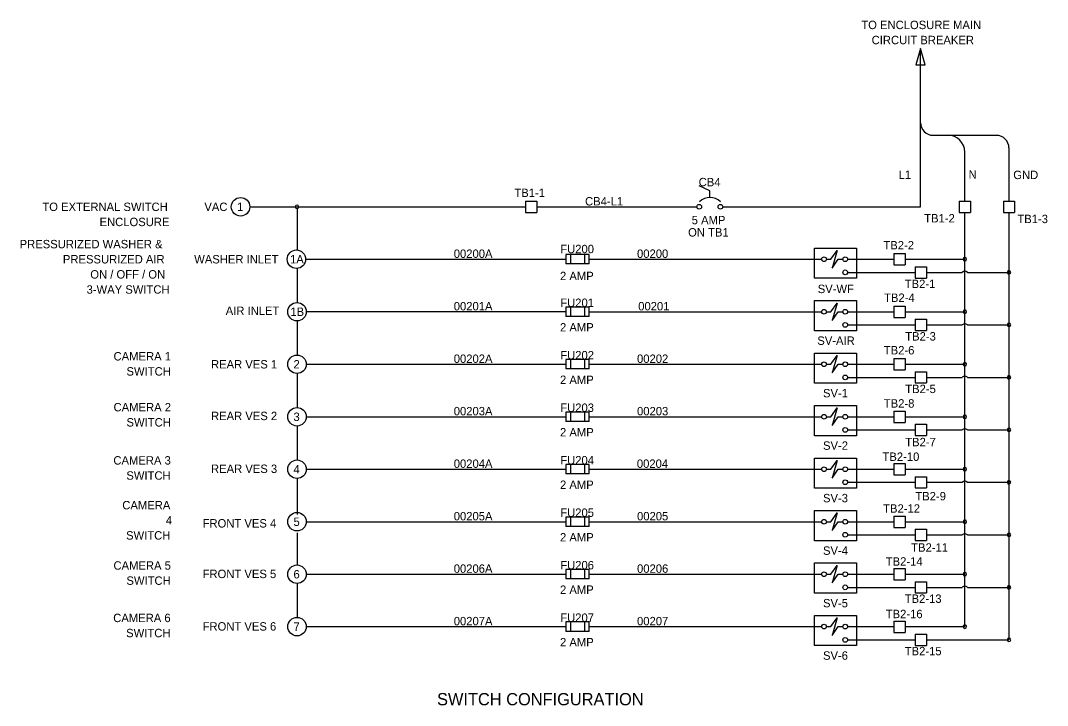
# Model space of a CAD drawing. Extents: x 0.81 to 2.03, y 0.91 to 1.72.
import ezdxf

# ---------------------------------------------------------------- set-up
doc = ezdxf.new("R2010")
doc.units = 0
for name, color, linetype in [('Default', 7, 'Continuous'), ('Sheets_General Details - Sheet Number Text', 7, 'Continuous'), ('Sheets_General Details - Total Sheet Number Text', 7, 'Continuous'), ('Sheets_General Details - Version Text', 7, 'Continuous')]:
    doc.layers.add(name, color=color, linetype=linetype)

# ---------------------------------------------------------------- blocks, each defined once
blk = doc.blocks.new('DOT-F')
at = {"layer": 'Default'}
for start, end in [(0, 180), (180, 0)]:
    blk.add_arc((0, 0), 0.000397, start, end, dxfattribs=at)
blk = doc.blocks.new('ARROW')
at = {"layer": 'Default'}
blk.add_lwpolyline([(0, 0), (-0.00556, 0.00159), (-0.00556, -0.00159)], close=True, dxfattribs=at)

msp = doc.modelspace()

# ---------------------------------------------------------------- linework, layer by layer
at = {"layer": 'Sheets_General Details - Sheet Number Text'}
for p, q in [((1.8822, 1.4994), (1.8822, 1.6878)), ((1.8971, 1.5845), (1.915, 1.5845)), ((1.915, 1.5845), (1.9726, 1.5845)), ((1.9875, 1.5695), (1.9875, 1.5062)), ((1.9349, 1.5062), (1.9349, 1.5646)), ((1.0837, 1.4994), (1.4119, 1.4994)), ((1.4253, 1.4994), (1.6159, 1.4994)), ((1.6467, 1.4994), (1.8822, 1.4994)), ((1.9349, 0.9997), (1.9349, 1.4927)), ((1.9875, 1.4927), (1.9875, 0.984)), ((1.151, 1.437), (1.4596, 1.437)), ((1.4876, 1.437), (1.7645, 1.437)), ((1.7953, 1.437), (1.8505, 1.437)), ((1.8639, 1.437), (1.9349, 1.437)), ((1.7953, 1.4214), (1.876, 1.4214)), ((1.8894, 1.4214), (1.9316, 1.4214)), ((1.9381, 1.4214), (1.9875, 1.4214)), ((1.4598, 1.3745), (1.151, 1.3745)), ((1.4876, 1.3745), (1.7645, 1.3745)), ((1.7953, 1.3745), (1.8505, 1.3745)), ((1.8639, 1.3745), (1.9349, 1.3745)), ((1.7953, 1.3589), (1.876, 1.3589)), ((1.8894, 1.3589), (1.9316, 1.3589)), ((1.9381, 1.3589), (1.9875, 1.3589)), ((1.151, 1.312), (1.4596, 1.312)), ((1.4876, 1.312), (1.7645, 1.312)), ((1.7953, 1.312), (1.8505, 1.312)), ((1.8639, 1.312), (1.9349, 1.312)), ((1.7953, 1.2964), (1.876, 1.2964)), ((1.8894, 1.2964), (1.9316, 1.2964)), ((1.9381, 1.2964), (1.9875, 1.2964)), ((1.1515, 1.2495), (1.4596, 1.2495)), ((1.4876, 1.2495), (1.7645, 1.2495)), ((1.7953, 1.2495), (1.8505, 1.2495)), ((1.8639, 1.2495), (1.9349, 1.2495)), ((1.7953, 1.2339), (1.876, 1.2339)), ((1.8894, 1.2339), (1.9316, 1.2339)), ((1.9381, 1.2339), (1.9875, 1.2339)), ((1.151, 1.1871), (1.4596, 1.1871)), ((1.4876, 1.1871), (1.7645, 1.1871)), ((1.7953, 1.1871), (1.8505, 1.1871)), ((1.8639, 1.1871), (1.9349, 1.1871)), ((1.7953, 1.1715), (1.876, 1.1715)), ((1.8894, 1.1715), (1.9316, 1.1715)), ((1.9381, 1.1715), (1.9875, 1.1715)), ((1.151, 1.1246), (1.4598, 1.1246)), ((1.4876, 1.1246), (1.7645, 1.1246)), ((1.7953, 1.1246), (1.8505, 1.1246)), ((1.8639, 1.1246), (1.9349, 1.1246)), ((1.7953, 1.109), (1.876, 1.109)), ((1.8894, 1.109), (1.9316, 1.109)), ((1.9381, 1.109), (1.9875, 1.109)), ((1.151, 1.0621), (1.4596, 1.0621)), ((1.4876, 1.0621), (1.7645, 1.0621)), ((1.7953, 1.0621), (1.8505, 1.0621)), ((1.8639, 1.0621), (1.9349, 1.0621)), ((1.7953, 1.0465), (1.876, 1.0465)), ((1.8894, 1.0465), (1.9316, 1.0465)), ((1.9381, 1.0465), (1.9875, 1.0465)), ((1.151, 0.9997), (1.4596, 0.9997)), ((1.4876, 0.9997), (1.7645, 0.9997)), ((1.7953, 0.9997), (1.8505, 0.9997)), ((1.8639, 0.9997), (1.9349, 0.9997)), ((1.7953, 0.984), (1.876, 0.984)), ((1.8894, 0.984), (1.9381, 0.984)), ((1.9381, 0.984), (1.9875, 0.984))]:
    msp.add_line(p, q, dxfattribs=at)
for centre, radius, start, end in [((1.8971, 1.5994), 0.0149, 180, 270), ((1.915, 1.5646), 0.0199, 360, 90), ((1.9726, 1.5695), 0.0149, 360, 90), ((1.9349, 1.418), 0.00466, 45.849, 134.151), ((1.9349, 1.3555), 0.00466, 45.849, 134.151), ((1.9349, 1.2931), 0.00466, 45.849, 134.151), ((1.9349, 1.2306), 0.00466, 45.849, 134.151), ((1.9349, 1.1681), 0.00466, 45.849, 134.151), ((1.9349, 1.1056), 0.00466, 45.849, 134.151), ((1.9349, 1.0432), 0.00466, 45.849, 134.151)]:
    msp.add_arc(centre, radius, start, end, dxfattribs=at)
at = {"layer": 'Sheets_General Details - Total Sheet Number Text'}
for p, q in [((1.1399, 1.4975), (1.1399, 1.448)), ((1.1399, 1.4259), (1.1399, 1.3855)), ((1.1399, 1.3635), (1.1399, 1.3231)), ((1.1399, 1.301), (1.1399, 1.2606)), ((1.1399, 1.2385), (1.1399, 1.1981)), ((1.1399, 1.176), (1.1399, 1.1333)), ((1.1399, 1.1112), (1.1399, 1.0732)), ((1.1399, 1.0511), (1.1399, 1.0107))]:
    msp.add_line(p, q, dxfattribs=at)
for centre in [(1.0727, 1.4994), (1.1392, 1.437), (1.1399, 1.3745), (1.1399, 1.312), (1.1399, 1.2495), (1.1399, 1.1871), (1.1399, 1.1246), (1.1399, 1.0621), (1.1399, 0.9997)]:
    msp.add_circle(centre, 0.011, dxfattribs=at)
at = {"layer": 'Sheets_General Details - Version Text'}
for p, q in [((1.6315, 1.5184), (1.6185, 1.5244)), ((1.6315, 1.5104), (1.6315, 1.5184)), ((1.4119, 1.5062), (1.4253, 1.5062)), ((1.4119, 1.5062), (1.4119, 1.4927)), ((1.4253, 1.5062), (1.4253, 1.4927)), ((1.9281, 1.5062), (1.9416, 1.5062)), ((1.9281, 1.5062), (1.9281, 1.4927)), ((1.9416, 1.5062), (1.9416, 1.4927)), ((1.9808, 1.5062), (1.9942, 1.5062)), ((1.9808, 1.5062), (1.9808, 1.4927)), ((1.9942, 1.5062), (1.9942, 1.4927)), ((1.4119, 1.4927), (1.4253, 1.4927)), ((1.9281, 1.4927), (1.9416, 1.4927)), ((1.9808, 1.4927), (1.9942, 1.4927)), ((1.7756, 1.437), (1.7828, 1.4474)), ((1.7828, 1.4474), (1.777, 1.4265)), ((1.8505, 1.4437), (1.8639, 1.4437)), ((1.8505, 1.4437), (1.8505, 1.4303)), ((1.8639, 1.4437), (1.8639, 1.4303)), ((1.4878, 1.4426), (1.4598, 1.4426)), ((1.4598, 1.4426), (1.4598, 1.4314)), ((1.4878, 1.4314), (1.4598, 1.4314)), ((1.4654, 1.4426), (1.4654, 1.4314)), ((1.4822, 1.4426), (1.4822, 1.4314)), ((1.4878, 1.4314), (1.4878, 1.4426)), ((1.7701, 1.437), (1.7756, 1.437)), ((1.777, 1.4265), (1.7842, 1.437)), ((1.7842, 1.437), (1.7897, 1.437)), ((1.8505, 1.4303), (1.8639, 1.4303)), ((1.876, 1.4281), (1.8894, 1.4281)), ((1.876, 1.4281), (1.876, 1.4146)), ((1.8894, 1.4281), (1.8894, 1.4146)), ((1.876, 1.4146), (1.8894, 1.4146)), ((1.7756, 1.3745), (1.7828, 1.3849)), ((1.7828, 1.3849), (1.777, 1.3641)), ((1.4878, 1.3801), (1.4598, 1.3801)), ((1.4598, 1.3801), (1.4598, 1.3689)), ((1.4654, 1.3801), (1.4654, 1.3689)), ((1.4822, 1.3801), (1.4822, 1.3689)), ((1.4878, 1.3689), (1.4878, 1.3801)), ((1.7701, 1.3745), (1.7756, 1.3745)), ((1.777, 1.3641), (1.7842, 1.3745)), ((1.7842, 1.3745), (1.7897, 1.3745)), ((1.8505, 1.3812), (1.8639, 1.3812)), ((1.8505, 1.3812), (1.8505, 1.3678)), ((1.8639, 1.3812), (1.8639, 1.3678)), ((1.4878, 1.3689), (1.4598, 1.3689)), ((1.8505, 1.3678), (1.8639, 1.3678)), ((1.876, 1.3656), (1.8894, 1.3656)), ((1.876, 1.3656), (1.876, 1.3522)), ((1.8894, 1.3656), (1.8894, 1.3522)), ((1.876, 1.3522), (1.8894, 1.3522)), ((1.7756, 1.312), (1.7828, 1.3225)), ((1.7828, 1.3225), (1.777, 1.3016)), ((1.4598, 1.3176), (1.4598, 1.3064)), ((1.4878, 1.3176), (1.4598, 1.3176)), ((1.4654, 1.3176), (1.4654, 1.3064)), ((1.4822, 1.3176), (1.4822, 1.3064)), ((1.4878, 1.3064), (1.4878, 1.3176)), ((1.7701, 1.312), (1.7756, 1.312)), ((1.777, 1.3016), (1.7842, 1.312)), ((1.7842, 1.312), (1.7897, 1.312)), ((1.8505, 1.3187), (1.8639, 1.3187)), ((1.8505, 1.3187), (1.8505, 1.3053)), ((1.8639, 1.3187), (1.8639, 1.3053)), ((1.4878, 1.3064), (1.4598, 1.3064)), ((1.8505, 1.3053), (1.8639, 1.3053)), ((1.876, 1.3031), (1.8894, 1.3031)), ((1.876, 1.3031), (1.876, 1.2897)), ((1.8894, 1.3031), (1.8894, 1.2897)), ((1.876, 1.2897), (1.8894, 1.2897)), ((1.7756, 1.2495), (1.7828, 1.26)), ((1.7828, 1.26), (1.777, 1.2391)), ((1.4598, 1.2551), (1.4598, 1.244)), ((1.4878, 1.2551), (1.4598, 1.2551)), ((1.4654, 1.2551), (1.4654, 1.244)), ((1.4822, 1.2551), (1.4822, 1.244)), ((1.4878, 1.244), (1.4878, 1.2551)), ((1.7701, 1.2495), (1.7756, 1.2495)), ((1.777, 1.2391), (1.7842, 1.2495)), ((1.7842, 1.2495), (1.7897, 1.2495)), ((1.8505, 1.2563), (1.8639, 1.2563)), ((1.8505, 1.2563), (1.8505, 1.2428)), ((1.8639, 1.2563), (1.8639, 1.2428)), ((1.4878, 1.244), (1.4598, 1.244)), ((1.8505, 1.2428), (1.8639, 1.2428)), ((1.876, 1.2407), (1.8894, 1.2407)), ((1.876, 1.2407), (1.876, 1.2272)), ((1.8894, 1.2407), (1.8894, 1.2272)), ((1.876, 1.2272), (1.8894, 1.2272)), ((1.4598, 1.1927), (1.4598, 1.1815)), ((1.4878, 1.1927), (1.4598, 1.1927)), ((1.4654, 1.1927), (1.4654, 1.1815)), ((1.4822, 1.1927), (1.4822, 1.1815)), ((1.4878, 1.1815), (1.4878, 1.1927)), ((1.7701, 1.1871), (1.7756, 1.1871)), ((1.7756, 1.1871), (1.7828, 1.1975)), ((1.7828, 1.1975), (1.777, 1.1766)), ((1.777, 1.1766), (1.7842, 1.1871)), ((1.7842, 1.1871), (1.7897, 1.1871)), ((1.8505, 1.1938), (1.8639, 1.1938)), ((1.8505, 1.1938), (1.8505, 1.1804)), ((1.8639, 1.1938), (1.8639, 1.1804)), ((1.4878, 1.1815), (1.4598, 1.1815)), ((1.8505, 1.1804), (1.8639, 1.1804)), ((1.876, 1.1782), (1.8894, 1.1782)), ((1.876, 1.1782), (1.876, 1.1648)), ((1.8894, 1.1782), (1.8894, 1.1648)), ((1.876, 1.1648), (1.8894, 1.1648)), ((1.4878, 1.1302), (1.4598, 1.1302)), ((1.4598, 1.1302), (1.4598, 1.119)), ((1.4654, 1.1302), (1.4654, 1.119)), ((1.4822, 1.1302), (1.4822, 1.119)), ((1.4878, 1.119), (1.4878, 1.1302)), ((1.7756, 1.1246), (1.7828, 1.135)), ((1.7828, 1.135), (1.777, 1.1142)), ((1.8505, 1.1313), (1.8639, 1.1313)), ((1.8505, 1.1313), (1.8505, 1.1179)), ((1.8639, 1.1313), (1.8639, 1.1179)), ((1.4878, 1.119), (1.4598, 1.119)), ((1.7701, 1.1246), (1.7756, 1.1246)), ((1.777, 1.1142), (1.7842, 1.1246)), ((1.7842, 1.1246), (1.7897, 1.1246)), ((1.8505, 1.1179), (1.8639, 1.1179)), ((1.876, 1.1157), (1.8894, 1.1157)), ((1.876, 1.1157), (1.876, 1.1023)), ((1.8894, 1.1157), (1.8894, 1.1023)), ((1.876, 1.1023), (1.8894, 1.1023)), ((1.4878, 1.0677), (1.4598, 1.0677)), ((1.4598, 1.0677), (1.4598, 1.0565)), ((1.4654, 1.0677), (1.4654, 1.0565)), ((1.4822, 1.0677), (1.4822, 1.0565)), ((1.4878, 1.0565), (1.4878, 1.0677)), ((1.7756, 1.0621), (1.7828, 1.0726)), ((1.7828, 1.0726), (1.777, 1.0517)), ((1.8505, 1.0688), (1.8639, 1.0688)), ((1.8505, 1.0688), (1.8505, 1.0554)), ((1.8639, 1.0688), (1.8639, 1.0554)), ((1.4878, 1.0565), (1.4598, 1.0565)), ((1.7701, 1.0621), (1.7756, 1.0621)), ((1.777, 1.0517), (1.7842, 1.0621)), ((1.7842, 1.0621), (1.7897, 1.0621)), ((1.8505, 1.0554), (1.8639, 1.0554)), ((1.876, 1.0532), (1.8894, 1.0532)), ((1.876, 1.0532), (1.876, 1.0398)), ((1.8894, 1.0532), (1.8894, 1.0398)), ((1.876, 1.0398), (1.8894, 1.0398)), ((1.4878, 1.0053), (1.4598, 1.0053)), ((1.4598, 1.0053), (1.4598, 0.9941)), ((1.4654, 1.0053), (1.4654, 0.9941)), ((1.4822, 1.0053), (1.4822, 0.9941)), ((1.4878, 0.9941), (1.4878, 1.0053)), ((1.7756, 0.9997), (1.7828, 1.0101)), ((1.7828, 1.0101), (1.777, 0.9892)), ((1.8505, 1.0064), (1.8639, 1.0064)), ((1.8505, 1.0064), (1.8505, 0.9929)), ((1.8639, 1.0064), (1.8639, 0.9929)), ((1.4878, 0.9941), (1.4598, 0.9941)), ((1.7701, 0.9997), (1.7756, 0.9997)), ((1.777, 0.9892), (1.7842, 0.9997)), ((1.7842, 0.9997), (1.7897, 0.9997)), ((1.8505, 0.9929), (1.8639, 0.9929)), ((1.876, 0.9908), (1.8894, 0.9908)), ((1.876, 0.9908), (1.876, 0.9773)), ((1.8894, 0.9908), (1.8894, 0.9773)), ((1.876, 0.9773), (1.8894, 0.9773))]:
    msp.add_line(p, q, dxfattribs=at)
for points in [[(1.7559, 1.4503), (1.8061, 1.4503), (1.8061, 1.4144), (1.7559, 1.4144)], [(1.7559, 1.3878), (1.8061, 1.3878), (1.8061, 1.3519), (1.7559, 1.3519)], [(1.7559, 1.3253), (1.8061, 1.3253), (1.8061, 1.2894), (1.7559, 1.2894)], [(1.7559, 1.2629), (1.8061, 1.2629), (1.8061, 1.227), (1.7559, 1.227)], [(1.7559, 1.2004), (1.8061, 1.2004), (1.8061, 1.1645), (1.7559, 1.1645)], [(1.7559, 1.1379), (1.8061, 1.1379), (1.8061, 1.102), (1.7559, 1.102)], [(1.7559, 1.0755), (1.8061, 1.0755), (1.8061, 1.0395), (1.7559, 1.0395)], [(1.7559, 1.013), (1.8061, 1.013), (1.8061, 0.9771), (1.7559, 0.9771)]]:
    msp.add_lwpolyline(points, close=True, dxfattribs=at)
for centre in [(1.6187, 1.4994), (1.6439, 1.4994), (1.7673, 1.437), (1.7925, 1.437), (1.7925, 1.4214), (1.7673, 1.3745), (1.7925, 1.3745), (1.7925, 1.3589), (1.7673, 1.312), (1.7925, 1.312), (1.7925, 1.2964), (1.7673, 1.2495), (1.7925, 1.2495), (1.7925, 1.2339), (1.7673, 1.1871), (1.7925, 1.1871), (1.7925, 1.1715), (1.7673, 1.1246), (1.7925, 1.1246), (1.7925, 1.109), (1.7673, 1.0621), (1.7925, 1.0621), (1.7925, 1.0465), (1.7673, 0.9997), (1.7925, 0.9997), (1.7925, 0.984)]:
    msp.add_circle(centre, 0.00279, dxfattribs=at)
msp.add_arc((1.6315, 1.4923), 0.0181, 46.3583, 133.6417, dxfattribs=at)

# ---------------------------------------------------------------- block references
at = {"layer": 'Sheets_General Details - Sheet Number Text'}
for name, p, xscale, yscale, rotation in [('ARROW', (1.8822, 1.6878), 3.524598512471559, 3.524598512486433, 89.99999999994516), ('DOT-F', (1.1399, 1.4994), 5.28689776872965, 5.286897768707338, -5.484581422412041e-11), ('DOT-F', (1.9349, 1.437), 5.28689776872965, 5.286897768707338, -5.484581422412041e-11), ('DOT-F', (1.9875, 1.4214), 5.28689776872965, 5.286897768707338, -5.484581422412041e-11), ('DOT-F', (1.9349, 1.3745), 5.28689776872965, 5.286897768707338, -5.484581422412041e-11), ('DOT-F', (1.9875, 1.3589), 5.28689776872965, 5.286897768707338, -5.484581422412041e-11), ('DOT-F', (1.9349, 1.312), 5.28689776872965, 5.286897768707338, -5.484581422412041e-11), ('DOT-F', (1.9875, 1.2964), 5.28689776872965, 5.286897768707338, -5.484581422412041e-11), ('DOT-F', (1.9349, 1.2495), 5.28689776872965, 5.286897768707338, -5.484581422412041e-11), ('DOT-F', (1.9875, 1.2339), 5.28689776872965, 5.286897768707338, -5.484581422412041e-11), ('DOT-F', (1.9349, 1.1871), 5.28689776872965, 5.286897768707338, -5.484581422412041e-11), ('DOT-F', (1.9875, 1.1715), 5.28689776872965, 5.286897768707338, -5.484581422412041e-11), ('DOT-F', (1.9349, 1.1246), 5.28689776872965, 5.286897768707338, -5.484581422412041e-11), ('DOT-F', (1.9875, 1.109), 5.28689776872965, 5.286897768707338, -5.484581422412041e-11), ('DOT-F', (1.9349, 1.0621), 5.28689776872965, 5.286897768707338, -5.484581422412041e-11), ('DOT-F', (1.9875, 1.0465), 5.28689776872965, 5.286897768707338, -5.484581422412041e-11), ('DOT-F', (1.9349, 0.9997), 5.28689776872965, 5.286897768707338, -5.484581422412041e-11), ('DOT-F', (1.9875, 0.984), 5.28689776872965, 5.286897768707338, -5.484581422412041e-11)]:
    msp.add_blockref(name, p, dxfattribs=dict(at, xscale=xscale, yscale=yscale, rotation=rotation))

# ---------------------------------------------------------------- texts
at = {"layer": 'Sheets_General Details - Total Sheet Number Text'}
for s, p in [('TO ENCLOSURE MAIN ', (1.8117, 1.7109)), ('CIRCUIT BREAKER', (1.824, 1.6929)), ('L1', (1.8561, 1.5326)), ('N', (1.9394, 1.5329)), ('GND', (1.9926, 1.5324)), ('CB4', (1.6181, 1.5238)), ('TB1-1', (1.3987, 1.5111)), ('TO EXTERNAL SWITCH', (0.8367, 1.4944)), ('VAC', (1.0296, 1.4944)), ('1', (1.0685, 1.4944)), ('CB4-L1', (1.4828, 1.501)), (' ENCLOSURE', (0.9011, 1.4764)), ('5 AMP', (1.6098, 1.4786)), ('TB1-2', (1.8866, 1.4808)), ('TB1-3', (1.9975, 1.48)), ('ON TB1', (1.6055, 1.464)), ('PRESSURIZED WASHER & ', (0.8097, 1.45)), ('TB2-2', (1.838, 1.4487)), ('00200A', (1.3265, 1.4386)), ('FU200', (1.4533, 1.4442)), ('00200', (1.5447, 1.4386)), ('PRESSURIZED AIR ', (0.8612, 1.432)), ('WASHER INLET', (1.0175, 1.432)), ('1A', (1.1316, 1.432)), ('ON / OFF / ON ', (0.8938, 1.414)), ('2 AMP', (1.453, 1.4121)), ('3-WAY SWITCH', (0.8894, 1.396)), ('SV-WF', (1.7598, 1.3967)), ('TB2-1', (1.8634, 1.4027)), ('TB2-4', (1.8388, 1.3862)), ('00201A', (1.3265, 1.3761)), ('FU201', (1.4533, 1.3802)), ('00201', (1.5461, 1.3761)), ('AIR INLET', (1.055, 1.3707)), ('1B', (1.132, 1.3695)), ('2 AMP', (1.453, 1.351)), ('SV-AIR', (1.7593, 1.3351)), ('TB2-3', (1.864, 1.3402)), ('TB2-6', (1.8385, 1.3237)), ('CAMERA 1', (0.9215, 1.3165)), ('00202A', (1.3265, 1.3136)), ('FU202', (1.4533, 1.3178)), ('00202', (1.5447, 1.3136)), (' SWITCH', (0.9332, 1.2985)), ('REAR VES 1', (1.0375, 1.307)), ('2', (1.1357, 1.307)), ('2 AMP', (1.453, 1.2885)), ('TB2-5', (1.864, 1.2777)), ('SV-1', (1.7661, 1.2726)), ('CAMERA 2', (0.9215, 1.2559)), ('00203A', (1.3265, 1.2512)), ('FU203', (1.4533, 1.2553)), ('00203', (1.5447, 1.2512)), ('TB2-8', (1.8385, 1.2604)), (' SWITCH', (0.9332, 1.2379)), ('REAR VES 2', (1.0375, 1.2455)), ('3', (1.1357, 1.2445)), ('2 AMP', (1.453, 1.2261)), ('TB2-7', (1.864, 1.2144)), ('SV-2', (1.7661, 1.2102)), ('CAMERA 3', (0.9213, 1.1926)), ('00204A', (1.3265, 1.1887)), ('FU204', (1.4533, 1.1928)), ('00204', (1.5445, 1.1887)), ('TB2-10', (1.8369, 1.197)), ('REAR VES 3', (1.0375, 1.1826)), ('4', (1.1357, 1.1821)), (' SWITCH', (0.933, 1.1746)), ('2 AMP', (1.453, 1.1636)), ('CAMERA', (0.9319, 1.1393)), ('SV-3', (1.7661, 1.1477)), ('TB2-9', (1.876, 1.15)), ('FU205', (1.4533, 1.1304)), ('TB2-12', (1.8377, 1.1353)), (' 4', (0.9801, 1.1213)), ('FRONT VES 4', (1.0275, 1.1177)), ('5', (1.1357, 1.1196)), ('00205A', (1.3265, 1.1262)), ('00205', (1.5447, 1.1262)), (' SWITCH', (0.9327, 1.1033)), ('2 AMP', (1.453, 1.1011)), ('SV-4', (1.7661, 1.0852)), ('TB2-11', (1.8711, 1.0889)), ('CAMERA 5', (0.9214, 1.0675)), ('FU206', (1.4533, 1.0679)), ('TB2-14', (1.8408, 1.0723)), ('FRONT VES 5', (1.0275, 1.0575)), ('6', (1.1357, 1.0571)), ('00206A', (1.3265, 1.0638)), ('00206', (1.5447, 1.0638)), (' SWITCH', (0.9331, 1.0495)), ('2 AMP', (1.453, 1.0387)), ('SV-5', (1.7661, 1.0227)), ('TB2-13', (1.8634, 1.028)), ('CAMERA 6', (0.9211, 1.0051)), ('FU207', (1.4533, 1.0054)), ('TB2-16', (1.8408, 1.0098)), ('FRONT VES 6', (1.0275, 0.995)), ('7', (1.1357, 0.9947)), ('00207A', (1.3265, 1.0013)), ('00207', (1.5447, 1.0013)), (' SWITCH', (0.9328, 0.9871)), ('2 AMP', (1.453, 0.9762)), ('SV-6', (1.7661, 0.9603)), ('TB2-15', (1.8634, 0.9656))]:
    msp.add_text(s, height=0.01, rotation=360, dxfattribs=at).set_placement(p)
msp.add_text('SWITCH CONFIGURATION', height=0.014583, dxfattribs=at).set_placement((1.3066, 0.9061))

doc.saveas('drawing.dxf')
